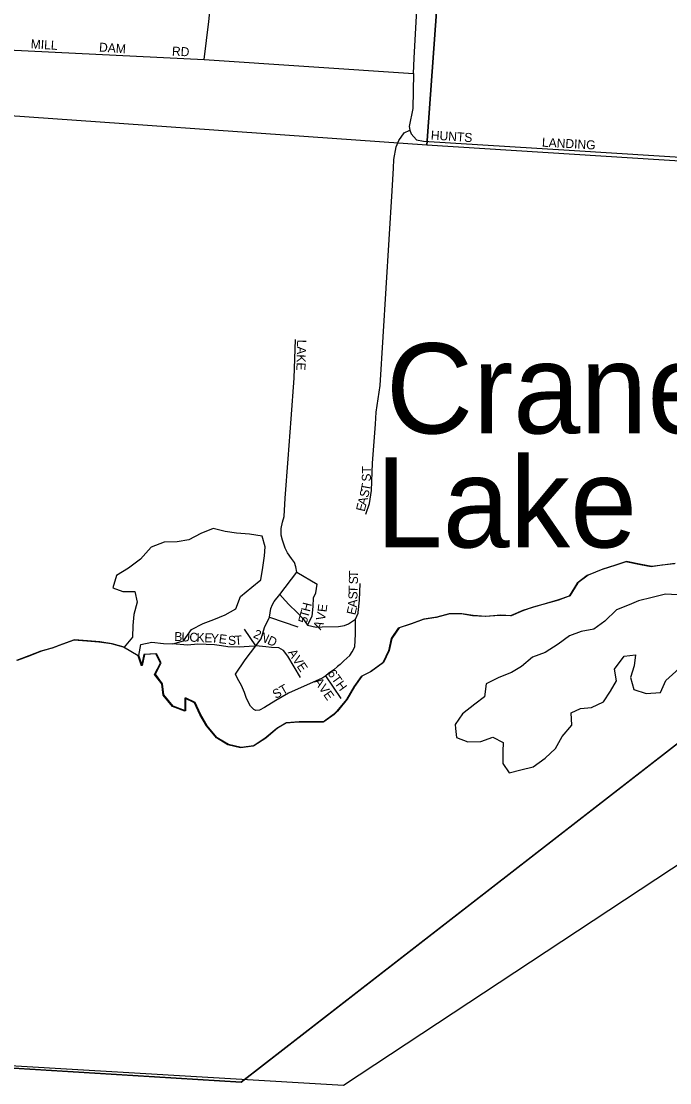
# Model space of a CAD drawing. Extents: x 0 to 40.4, y 0 to 22.
# Drawn here: x 7.206 to 7.886, y 14.615 to 15.73 of the extents above; entities that cross this region are included whole.
import ezdxf

# ---------------------------------------------------------------- set-up
doc = ezdxf.new("R2010")
doc.units = 0
for name, color, linetype in [('GM_X_City_Street', 7, 'Continuous'), ('GM_X_City_Street_Text', 7, 'Continuous'), ('GM_X_Corporation', 7, 'Continuous'), ('GM_X_County', 7, 'Continuous'), ('GM_X_Major_Lake', 7, 'Continuous'), ('GM_X_Minor_Lake_Text', 7, 'Continuous'), ('GM_X_Section', 7, 'Continuous')]:
    doc.layers.add(name, color=color, linetype=linetype)

msp = doc.modelspace()

# ---------------------------------------------------------------- linework, layer by layer
at = {"layer": 'GM_X_City_Street'}
for points in [[(7.1916, 15.6998), (7.3976, 15.6894), (7.6176, 15.6748), (7.6181, 15.6909), (7.6244, 15.8052), (7.6307, 15.9128), (7.636, 16.0217)], [(7.3976, 15.6894), (7.4025, 15.7294), (7.4053, 15.7564), (7.406, 15.762), (7.4056, 15.7655), (7.4052, 15.7677), (7.4041, 15.7708), (7.4022, 15.7734), (7.3999, 15.776), (7.3972, 15.7775), (7.3938, 15.7783), (7.3893, 15.779), (7.2415, 15.7879), (7.2118, 15.7897)], [(7.6176, 15.6748), (7.6167, 15.6381), (7.6129, 15.6192), (7.6135, 15.6152), (7.615, 15.6115), (7.6206, 15.6052), (7.6279, 15.6039), (7.781, 15.5944), (8.1089, 15.5735), (8.127, 15.57)], [(7.5673, 15.212), (7.5714, 15.2233), (7.5732, 15.2368), (7.5745, 15.2655), (7.5776, 15.3064), (7.5784, 15.319), (7.5823, 15.3472), (7.595, 15.5516), (7.5964, 15.5755), (7.5967, 15.5844), (7.5991, 15.5977), (7.602, 15.6044), (7.6076, 15.6124), (7.6135, 15.6152)], [(7.5216, 15.0397), (7.5215, 15.0397), (7.4861, 15.0241), (7.4731, 15.0162), (7.4612, 15.0089), (7.4557, 15.0061), (7.4519, 15.0057), (7.45, 15.0069), (7.4465, 15.0105), (7.4421, 15.0184), (7.4402, 15.0246), (7.437, 15.032), (7.4327, 15.0395), (7.4307, 15.0439), (7.4408, 15.0591), (7.452, 15.0736), (7.4574, 15.0812), (7.461, 15.0929), (7.4664, 15.1038), (7.4676, 15.1129), (7.4693, 15.1171), (7.4712, 15.1203), (7.4771, 15.1277), (7.4951, 15.1511), (7.4939, 15.1568), (7.4925, 15.1614), (7.4893, 15.1655), (7.4851, 15.1716), (7.4826, 15.1763), (7.4798, 15.1847), (7.4784, 15.1901), (7.4785, 15.1971), (7.4798, 15.2035), (7.4818, 15.2096), (7.4828, 15.229), (7.4859, 15.2702), (7.4892, 15.312), (7.4923, 15.355), (7.4937, 15.3953)], [(7.4951, 15.1511), (7.5164, 15.1387)], [(7.5594, 15.1089), (7.5607, 15.1216), (7.5613, 15.1393)], [(7.5062, 15.0956), (7.511, 15.1048), (7.512, 15.1149), (7.5126, 15.1241), (7.5148, 15.1295), (7.5164, 15.1387)], [(7.4771, 15.1277), (7.4829, 15.1213)], [(7.4829, 15.1213), (7.4869, 15.1169), (7.4949, 15.109), (7.5012, 15.1026), (7.5062, 15.0956)], [(7.5442, 15.0581), (7.5507, 15.0635), (7.553, 15.0676), (7.5559, 15.0728), (7.5567, 15.0859), (7.5567, 15.1018), (7.5593, 15.1079), (7.5594, 15.1089)], [(7.4664, 15.1038), (7.4959, 15.0937)], [(7.5062, 15.0956), (7.5153, 15.0935), (7.5217, 15.0937), (7.5387, 15.0941), (7.545, 15.0952), (7.5493, 15.0967), (7.5567, 15.1018)], [(7.4624, 15.0727), (7.452, 15.0736), (7.4401, 15.0914)], [(7.3646, 15.0762), (7.3803, 15.0748), (7.3911, 15.0758), (7.4084, 15.075), (7.416, 15.0742), (7.4225, 15.0732), (7.4343, 15.0728), (7.4449, 15.0734), (7.452, 15.0736)], [(7.4989, 15.0405), (7.4856, 15.063), (7.4811, 15.0687), (7.4761, 15.0718), (7.4685, 15.0721), (7.4624, 15.0727)], [(7.5442, 15.0581), (7.5405, 15.0543), (7.5375, 15.052), (7.5337, 15.0486), (7.5284, 15.0447), (7.5254, 15.0424), (7.5224, 15.0401), (7.5216, 15.0397)], [(7.5415, 15.0186), (7.5254, 15.0424)]]:
    msp.add_lwpolyline(points, dxfattribs=at)
at = {"layer": 'GM_X_Corporation'}
msp.add_lwpolyline([(7.8915, 15.1598), (7.8782, 15.1584), (7.8669, 15.1569), (7.8556, 15.1588), (7.8404, 15.1619), (7.8287, 15.1582), (7.8155, 15.1541), (7.7999, 15.1477), (7.7893, 15.1397), (7.7809, 15.1261), (7.7688, 15.1216), (7.7423, 15.1141), (7.7321, 15.1108), (7.7192, 15.1051), (7.7082, 15.1056), (7.6927, 15.1045), (7.6795, 15.1053), (7.6674, 15.1072), (7.6542, 15.1069), (7.6413, 15.1035), (7.6277, 15.1013), (7.6152, 15.0968), (7.6015, 15.0923), (7.5939, 15.0813), (7.5912, 15.0685), (7.5851, 15.056), (7.5722, 15.0465), (7.5624, 15.0416), (7.5548, 15.0307), (7.5472, 15.0174), (7.5369, 15.005), (7.5335, 15.0016), (7.5225, 14.9936), (7.4968, 14.9937), (7.4835, 14.9927), (7.4741, 14.987), (7.4615, 14.9764), (7.449, 14.9685), (7.4358, 14.9667), (7.4226, 14.9698), (7.4105, 14.977), (7.4, 14.9896), (7.3932, 15.0017), (7.3876, 15.0139), (7.3774, 15.0188), (7.3773, 15.0052), (7.3645, 15.0102), (7.3547, 15.022), (7.3532, 15.0337), (7.3457, 15.0436), (7.3518, 15.0557), (7.3469, 15.0652), (7.3345, 15.0645), (7.3318, 15.0528), (7.3284, 15.0634), (7.3129, 15.0722), (7.3005, 15.0757), (7.2872, 15.0776), (7.2744, 15.0788), (7.2608, 15.0796), (7.2483, 15.0751), (7.2381, 15.0713), (7.2263, 15.068), (7.2138, 15.0631), (7.2006, 15.0582)], dxfattribs=at)
at = {"layer": 'GM_X_County'}
msp.add_lwpolyline([(2.6, 14.9098), (3.7816, 14.849), (3.7947, 14.8444), (4.3781, 14.8049), (4.5187, 14.7962), (4.7718, 14.7855), (4.9113, 14.7777), (5.1259, 14.7632), (5.4221, 14.7453), (5.6303, 14.7317), (5.757, 14.7237), (5.765, 14.7235), (5.7951, 14.7228), (5.8513, 14.7168), (5.9456, 14.7103), (6.2034, 14.693), (6.2494, 14.69), (6.369, 14.682), (6.4224, 14.6785), (7.5441, 14.6124), (8.0846, 14.9692), (9.4, 14.8681)], dxfattribs=at)
at = {"layer": 'GM_X_Major_Lake'}
for p, q in [((7.4365, 14.6157), (8.0892, 15.1222)), ((6.4626, 14.6755), (7.4365, 14.6157))]:
    msp.add_line(p, q, dxfattribs=at)
for points in [[(7.354, 15.034), (7.3465, 15.0439), (7.3526, 15.056), (7.3477, 15.0655), (7.3352, 15.0648), (7.3325, 15.053), (7.3292, 15.0637), (7.3311, 15.075), (7.3428, 15.0777), (7.3549, 15.0761), (7.3648, 15.0757), (7.3761, 15.079), (7.3845, 15.0908), (7.3966, 15.0972), (7.408, 15.1013), (7.4197, 15.1062), (7.4311, 15.1126), (7.436, 15.1255), (7.4478, 15.1353), (7.4573, 15.1432), (7.4592, 15.1561), (7.4612, 15.1682), (7.4616, 15.1777), (7.4586, 15.1891), (7.4454, 15.191), (7.4318, 15.1922), (7.4197, 15.1938), (7.4072, 15.1969), (7.3943, 15.1916), (7.3815, 15.1852), (7.3693, 15.183), (7.3557, 15.1826), (7.3421, 15.1774), (7.3307, 15.1649), (7.3182, 15.1555), (7.3057, 15.1476), (7.3018, 15.1347), (7.3124, 15.1309), (7.3249, 15.1308), (7.3275, 15.1198), (7.3237, 15.1065), (7.3229, 15.0952), (7.3224, 15.083), (7.3137, 15.0725), (7.3012, 15.0759), (7.288, 15.0779), (7.2751, 15.0791), (7.2615, 15.0799), (7.249, 15.0754), (7.2388, 15.0716), (7.2271, 15.0682), (7.2146, 15.0634), (7.2013, 15.0585)], [(7.8922, 15.1601), (7.879, 15.1586), (7.8676, 15.1572), (7.8563, 15.1591), (7.8412, 15.1622), (7.8295, 15.1584), (7.8162, 15.1543), (7.8007, 15.1479), (7.7901, 15.14), (7.7817, 15.1264), (7.7696, 15.1219), (7.7431, 15.1144), (7.7328, 15.111), (7.72, 15.1054), (7.709, 15.1058), (7.6935, 15.1047), (7.6802, 15.1056), (7.6682, 15.1075), (7.6549, 15.1072), (7.642, 15.1038), (7.6284, 15.1016), (7.6159, 15.0971), (7.6023, 15.0926), (7.5947, 15.0816), (7.592, 15.0687), (7.5859, 15.0562), (7.573, 15.0468), (7.5631, 15.0419), (7.5555, 15.0309), (7.5479, 15.0177), (7.5377, 15.0052), (7.5342, 15.0018)], [(7.8947, 15.1275), (7.8819, 15.1279), (7.8679, 15.1245), (7.8535, 15.1212), (7.8437, 15.1167), (7.8304, 15.1114), (7.8182, 15.0997), (7.8069, 15.0914), (7.7936, 15.0888), (7.7811, 15.0843), (7.7694, 15.0756), (7.7557, 15.0666), (7.7425, 15.0617), (7.7307, 15.0519), (7.7205, 15.0459), (7.7072, 15.0406), (7.6939, 15.0338), (7.692, 15.0202), (7.6818, 15.0126), (7.6689, 15.0024), (7.6613, 14.9911)], [(8.0483, 14.5781), (8.0892, 15.1222), (7.4365, 14.6157), (6.4626, 14.6755)], [(7.6613, 14.9911), (7.6616, 14.9869), (7.6627, 14.9774), (7.6744, 14.9728), (7.688, 14.9732), (7.7009, 14.9777), (7.7115, 14.9723), (7.7111, 14.9628), (7.7114, 14.9503), (7.7178, 14.9404), (7.7303, 14.9434), (7.7431, 14.9468), (7.7556, 14.9558), (7.7667, 14.966), (7.7735, 14.9785), (7.7838, 14.9906), (7.7831, 15.0035), (7.7929, 15.008), (7.8043, 15.0091), (7.8168, 15.0148), (7.8244, 15.0261), (7.8305, 15.0371), (7.8283, 15.0492), (7.8385, 15.0628), (7.8506, 15.0643), (7.8491, 15.0526), (7.8452, 15.0404), (7.8486, 15.0279), (7.8618, 15.0237), (7.8766, 15.0248), (7.8823, 15.0373), (7.8963, 15.0501)], [(7.5342, 15.0018), (7.5232, 14.9939), (7.4975, 14.994), (7.4843, 14.9929), (7.4748, 14.9873), (7.4623, 14.9767), (7.4498, 14.9688), (7.4365, 14.9669), (7.4233, 14.97), (7.4112, 14.9773), (7.4007, 14.9898), (7.3939, 15.002), (7.3883, 15.0141), (7.3781, 15.0191), (7.3781, 15.0055), (7.3652, 15.0104), (7.3555, 15.0222), (7.354, 15.034)]]:
    msp.add_lwpolyline(points, dxfattribs=at)
at = {"layer": 'GM_X_Section'}
for points in [[(7.1996, 16.6471), (7.2909, 16.6427), (7.7054, 16.6198), (7.6314, 15.5996), (7.1143, 15.6359)], [(7.7054, 16.6198), (8.1953, 16.5941), (8.1289, 15.6484), (8.124, 15.5684), (7.6314, 15.5996)]]:
    msp.add_lwpolyline(points, close=True, dxfattribs=at)

# ---------------------------------------------------------------- texts
at = {"layer": 'GM_X_City_Street_Text'}
for s, rotation, p in [('MILL', 356.6354, (7.2154, 15.7012)), ('DAM', 355.9114, (7.2871, 15.6979)), ('RD', 356.989, (7.3637, 15.6937)), ('HUNTS', 356.266, (7.6354, 15.6055)), ('LANDING', 356.8654, (7.7521, 15.598)), ('LAKE', 268.4097, (7.4954, 15.3954)), ('ST', 90, (7.5727, 15.2463)), ('T', 79.59, (7.5714, 15.2358)), ('A', 76.2076, (7.5677, 15.2207)), ('S', 76.2089, (7.5697, 15.2288)), ('E', 76.2089, (7.5661, 15.2142)), ('T', 88.4501, (7.5592, 15.145)), ('S', 88.4363, (7.559, 15.1383)), ('S', 88.1848, (7.5585, 15.1224)), ('T', 88.4114, (7.5587, 15.1291)), ('H', 75.7787, (7.5086, 15.109)), ('E', 83.5888, (7.5261, 15.1088)), ('A', 86.6824, (7.558, 15.1138)), ('T', 74.8838, (7.5068, 15.1024)), ('V', 78.6557, (7.5243, 15.0997)), ('E', 76.9112, (7.5563, 15.1056)), ('5', 74.9037, (7.5053, 15.0967)), ('A', 64.686, (7.52, 15.0898)), ('B', 357.6919, (7.3662, 15.0789)), ('U', 357.6823, (7.3737, 15.0786)), ('C', 357.6676, (7.382, 15.0782)), ('K', 357.6959, (7.3895, 15.0779)), ('E', 357.6766, (7.3978, 15.0776)), ('Y', 356.0841, (7.4044, 15.0773)), ('E', 352.2447, (7.4126, 15.0768)), ('S', 0.683, (7.4228, 15.0747)), ('T', 4.1684, (7.4301, 15.0748)), ('2ND', 335.5628, (7.4485, 15.0829)), ('A', 300.9975, (7.4853, 15.0669)), ('V', 303.4895, (7.4899, 15.0594)), ('E', 303.6979, (7.4945, 15.0524)), ('AVE', 305.3105, (7.5126, 15.0362)), ('6TH', 305.5367, (7.5268, 15.0448)), ('ST', 29.7432, (7.4728, 15.0178))]:
    msp.add_text(s, height=0.00947, rotation=rotation, dxfattribs=at).set_placement(p)
at = {"layer": 'GM_X_Minor_Lake_Text'}
for s, rotation, p in [('Crane', 0.0002, (7.5885, 15.2968)), ('Lake', 0.0004, (7.5777, 15.1771))]:
    msp.add_text(s, height=0.09469, rotation=rotation, dxfattribs=at).set_placement(p)

doc.saveas('drawing.dxf')
